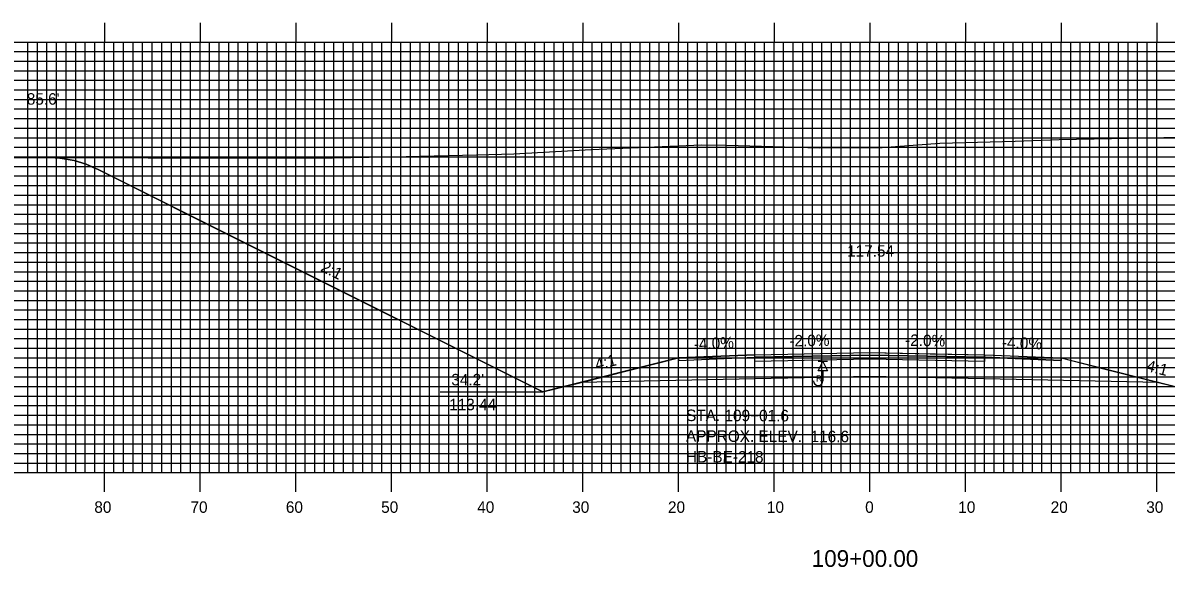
# Model space of a CAD drawing. Extents: x 1768874 to 1769217, y 442591 to 442811.
# Drawn here: x 1768951.5 to 1769071, y 442658.8 to 442715.7 of the extents above; entities that cross this region are included whole.
import ezdxf

# ---------------------------------------------------------------- set-up
doc = ezdxf.new("R2010")
doc.units = 0
for name, color, linetype in [('ANNOTATION', 7, 'Continuous'), ('BORING - REFUSAL', 7, 'Continuous'), ('D_Roadway_Centerline', 7, 'Continuous'), ('D_Roadway_Centerline_Text', 7, 'Continuous'), ('D_Roadway_Edge_Shoulder', 7, 'Continuous'), ('D_Roadway_Edge_TW', 7, 'Continuous'), ('D_Roadway_Pavement', 7, 'Continuous'), ('D_Roadway_SlopeLines', 7, 'Continuous'), ('D_Roadway_SubGrade', 7, 'Continuous'), ('D_Text_Standard', 7, 'Continuous'), ('H_V ANNOTATION', 7, 'Continuous'), ('MAJOR', 7, 'Continuous'), ('MINOR', 7, 'Continuous'), ('PDRAIN', 7, 'Continuous'), ('S_Roadway_Centerline', 7, 'Continuous')]:
    doc.layers.add(name, color=color, linetype=linetype)

msp = doc.modelspace()

# ---------------------------------------------------------------- linework, layer by layer
at = {"layer": 'BORING - REFUSAL'}
for p, q in [((1769035.57, 442680.27), (1769034.61, 442680.27)), ((1769035.09, 442679.31), (1769035.09, 442678.25))]:
    msp.add_line(p, q, dxfattribs=at)
msp.add_lwpolyline([(1769035.09, 442680.27), (1769035.57, 442679.31), (1769034.61, 442679.31)], close=True, dxfattribs=at)
msp.add_arc((1769034.6, 442678.25), 0.485, 180, 0, dxfattribs=at)
at = {"layer": 'D_Roadway_Centerline'}
msp.add_lwpolyline([(1768954.34, 442701.59), (1768955.34, 442701.52), (1768955.59, 442701.51), (1768956.84, 442701.28), (1768958.09, 442700.89), (1768958.75, 442700.6), (1768959.34, 442700.34), (1768975.05, 442692.48), (1769005.81, 442677.1), (1769009.82, 442678.1), (1769019.99, 442680.65), (1769027.99, 442680.97), (1769039.99, 442681.21), (1769046.29, 442681.08), (1769051.99, 442680.97), (1769059.99, 442680.65), (1769064.47, 442679.53), (1769070.16, 442678.1), (1769074.16, 442677.1)], dxfattribs=at)
at = {"layer": 'D_Roadway_Edge_Shoulder'}
for points in [[(1769027.99, 442680.97), (1769019.99, 442680.65), (1769019.99, 442680.4), (1769027.99, 442680.72)], [(1769051.99, 442680.97), (1769059.99, 442680.65), (1769059.99, 442680.4), (1769051.99, 442680.72)]]:
    msp.add_lwpolyline(points, close=True, dxfattribs=at)
at = {"layer": 'D_Roadway_Edge_TW'}
msp.add_lwpolyline([(1769027.99, 442680.72), (1769027.99, 442680.97), (1769039.99, 442681.21), (1769051.99, 442680.97), (1769051.99, 442680.72), (1769039.99, 442680.96)], close=True, dxfattribs=at)
at = {"layer": 'D_Roadway_Pavement'}
msp.add_lwpolyline([(1769027.99, 442680.3), (1769027.99, 442680.72), (1769039.99, 442680.96), (1769051.99, 442680.72), (1769051.99, 442680.3), (1769039.99, 442680.54)], close=True, dxfattribs=at)
at = {"layer": 'D_Roadway_SlopeLines'}
for points in [[(1769005.81, 442677.1), (1768959.34, 442700.34), (1768958.09, 442700.89), (1768956.84, 442701.28), (1768955.59, 442701.51), (1768954.34, 442701.59)], [(1769019.99, 442680.65), (1769005.81, 442677.1)], [(1769059.99, 442680.65), (1769074.16, 442677.1)]]:
    msp.add_lwpolyline(points, dxfattribs=at)
at = {"layer": 'D_Roadway_SubGrade'}
msp.add_lwpolyline([(1769027.99, 442678.47), (1769009.82, 442678.1), (1769019.99, 442680.65), (1769019.99, 442680.4), (1769027.99, 442680.72), (1769039.99, 442680.96), (1769051.99, 442680.72), (1769059.99, 442680.4), (1769059.99, 442680.65), (1769070.16, 442678.1), (1769051.99, 442678.47), (1769039.99, 442678.71)], close=True, dxfattribs=at)
at = {"layer": 'MAJOR'}
for p, q in [((1768959.99, 442715.67), (1768959.99, 442713.67)), ((1768969.99, 442715.67), (1768969.99, 442713.67)), ((1768979.99, 442715.67), (1768979.99, 442713.67)), ((1768989.99, 442715.67), (1768989.99, 442713.67)), ((1768999.99, 442715.67), (1768999.99, 442713.67)), ((1769009.99, 442715.67), (1769009.99, 442713.67)), ((1769019.99, 442715.67), (1769019.99, 442713.67)), ((1769029.99, 442715.67), (1769029.99, 442713.67)), ((1769039.99, 442715.67), (1769039.99, 442713.67)), ((1769049.99, 442715.67), (1769049.99, 442713.67)), ((1769059.99, 442715.67), (1769059.99, 442713.67)), ((1769069.99, 442715.67), (1769069.99, 442713.67)), ((1768899.99, 442713.67), (1769179.99, 442713.67)), ((1768899.99, 442713.67), (1769179.99, 442713.67)), ((1768959.99, 442668.67), (1768959.99, 442713.67)), ((1768969.99, 442668.67), (1768969.99, 442713.67)), ((1768979.99, 442668.67), (1768979.99, 442713.67)), ((1768989.99, 442668.67), (1768989.99, 442713.67)), ((1768999.99, 442668.67), (1768999.99, 442713.67)), ((1769009.99, 442668.67), (1769009.99, 442713.67)), ((1769019.99, 442668.67), (1769019.99, 442713.67)), ((1769029.99, 442668.67), (1769029.99, 442713.67)), ((1769039.99, 442668.67), (1769039.99, 442713.67)), ((1769049.99, 442668.67), (1769049.99, 442713.67)), ((1769059.99, 442668.67), (1769059.99, 442713.67)), ((1769069.99, 442668.67), (1769069.99, 442713.67)), ((1768899.99, 442708.67), (1769179.99, 442708.67)), ((1768899.99, 442703.67), (1769179.99, 442703.67)), ((1768899.99, 442698.67), (1769179.99, 442698.67)), ((1768899.99, 442693.67), (1769179.99, 442693.67)), ((1768899.99, 442688.67), (1769179.99, 442688.67)), ((1768899.99, 442683.67), (1769179.99, 442683.67)), ((1768899.99, 442678.67), (1769179.99, 442678.67)), ((1768899.99, 442673.67), (1769179.99, 442673.67)), ((1768899.99, 442668.67), (1769179.99, 442668.67)), ((1768899.99, 442668.67), (1769179.99, 442668.67)), ((1768959.99, 442666.66), (1768959.99, 442668.67)), ((1768969.99, 442666.66), (1768969.99, 442668.67)), ((1768979.99, 442666.66), (1768979.99, 442668.67)), ((1768989.99, 442666.66), (1768989.99, 442668.67)), ((1768999.99, 442666.66), (1768999.99, 442668.67)), ((1769009.99, 442666.66), (1769009.99, 442668.67)), ((1769019.99, 442666.66), (1769019.99, 442668.67)), ((1769029.99, 442666.66), (1769029.99, 442668.67)), ((1769039.99, 442666.66), (1769039.99, 442668.67)), ((1769049.99, 442666.66), (1769049.99, 442668.67)), ((1769059.99, 442666.66), (1769059.99, 442668.67)), ((1769069.99, 442666.66), (1769069.99, 442668.67))]:
    msp.add_line(p, q, dxfattribs=at)
at = {"layer": 'MINOR'}
for p, q in [((1768951.99, 442668.67), (1768951.99, 442713.67)), ((1768952.99, 442668.67), (1768952.99, 442713.67)), ((1768953.99, 442668.67), (1768953.99, 442713.67)), ((1768954.99, 442668.67), (1768954.99, 442713.67)), ((1768955.99, 442668.67), (1768955.99, 442713.67)), ((1768956.99, 442668.67), (1768956.99, 442713.67)), ((1768957.99, 442668.67), (1768957.99, 442713.67)), ((1768958.99, 442668.67), (1768958.99, 442713.67)), ((1768960.99, 442668.67), (1768960.99, 442713.67)), ((1768961.99, 442668.67), (1768961.99, 442713.67)), ((1768962.99, 442668.67), (1768962.99, 442713.67)), ((1768963.99, 442668.67), (1768963.99, 442713.67)), ((1768964.99, 442668.67), (1768964.99, 442713.67)), ((1768965.99, 442668.67), (1768965.99, 442713.67)), ((1768966.99, 442668.67), (1768966.99, 442713.67)), ((1768967.99, 442668.67), (1768967.99, 442713.67)), ((1768968.99, 442668.67), (1768968.99, 442713.67)), ((1768970.99, 442668.67), (1768970.99, 442713.67)), ((1768971.99, 442668.67), (1768971.99, 442713.67)), ((1768972.99, 442668.67), (1768972.99, 442713.67)), ((1768973.99, 442668.67), (1768973.99, 442713.67)), ((1768974.99, 442668.67), (1768974.99, 442713.67)), ((1768975.99, 442668.67), (1768975.99, 442713.67)), ((1768976.99, 442668.67), (1768976.99, 442713.67)), ((1768977.99, 442668.67), (1768977.99, 442713.67)), ((1768978.99, 442668.67), (1768978.99, 442713.67)), ((1768980.99, 442668.67), (1768980.99, 442713.67)), ((1768981.99, 442668.67), (1768981.99, 442713.67)), ((1768982.99, 442668.67), (1768982.99, 442713.67)), ((1768983.99, 442668.67), (1768983.99, 442713.67)), ((1768984.99, 442668.67), (1768984.99, 442713.67)), ((1768985.99, 442668.67), (1768985.99, 442713.67)), ((1768986.99, 442668.67), (1768986.99, 442713.67)), ((1768987.99, 442668.67), (1768987.99, 442713.67)), ((1768988.99, 442668.67), (1768988.99, 442713.67)), ((1768990.99, 442668.67), (1768990.99, 442713.67)), ((1768991.99, 442668.67), (1768991.99, 442713.67)), ((1768992.99, 442668.67), (1768992.99, 442713.67)), ((1768993.99, 442668.67), (1768993.99, 442713.67)), ((1768994.99, 442668.67), (1768994.99, 442713.67)), ((1768995.99, 442668.67), (1768995.99, 442713.67)), ((1768996.99, 442668.67), (1768996.99, 442713.67)), ((1768997.99, 442668.67), (1768997.99, 442713.67)), ((1768998.99, 442668.67), (1768998.99, 442713.67)), ((1769000.99, 442668.67), (1769000.99, 442713.67)), ((1769001.99, 442668.67), (1769001.99, 442713.67)), ((1769002.99, 442668.67), (1769002.99, 442713.67)), ((1769003.99, 442668.67), (1769003.99, 442713.67)), ((1769004.99, 442668.67), (1769004.99, 442713.67)), ((1769005.99, 442668.67), (1769005.99, 442713.67)), ((1769006.99, 442668.67), (1769006.99, 442713.67)), ((1769007.99, 442668.67), (1769007.99, 442713.67)), ((1769008.99, 442668.67), (1769008.99, 442713.67)), ((1769010.99, 442668.67), (1769010.99, 442713.67)), ((1769011.99, 442668.67), (1769011.99, 442713.67)), ((1769012.99, 442668.67), (1769012.99, 442713.67)), ((1769013.99, 442668.67), (1769013.99, 442713.67)), ((1769014.99, 442668.67), (1769014.99, 442713.67)), ((1769015.99, 442668.67), (1769015.99, 442713.67)), ((1769016.99, 442668.67), (1769016.99, 442713.67)), ((1769017.99, 442668.67), (1769017.99, 442713.67)), ((1769018.99, 442668.67), (1769018.99, 442713.67)), ((1769020.99, 442668.67), (1769020.99, 442713.67)), ((1769021.99, 442668.67), (1769021.99, 442713.67)), ((1769022.99, 442668.67), (1769022.99, 442713.67)), ((1769023.99, 442668.67), (1769023.99, 442713.67)), ((1769024.99, 442668.67), (1769024.99, 442713.67)), ((1769025.99, 442668.67), (1769025.99, 442713.67)), ((1769026.99, 442668.67), (1769026.99, 442713.67)), ((1769027.99, 442668.67), (1769027.99, 442713.67)), ((1769028.99, 442668.67), (1769028.99, 442713.67)), ((1769030.99, 442668.67), (1769030.99, 442713.67)), ((1769031.99, 442668.67), (1769031.99, 442713.67)), ((1769032.99, 442668.67), (1769032.99, 442713.67)), ((1769033.99, 442668.67), (1769033.99, 442713.67)), ((1769034.99, 442668.67), (1769034.99, 442713.67)), ((1769035.99, 442668.67), (1769035.99, 442713.67)), ((1769036.99, 442668.67), (1769036.99, 442713.67)), ((1769037.99, 442668.67), (1769037.99, 442713.67)), ((1769038.99, 442668.67), (1769038.99, 442713.67)), ((1769040.99, 442668.67), (1769040.99, 442713.67)), ((1769041.99, 442668.67), (1769041.99, 442713.67)), ((1769042.99, 442668.67), (1769042.99, 442713.67)), ((1769043.99, 442668.67), (1769043.99, 442713.67)), ((1769044.99, 442668.67), (1769044.99, 442713.67)), ((1769045.99, 442668.67), (1769045.99, 442713.67)), ((1769046.99, 442668.67), (1769046.99, 442713.67)), ((1769047.99, 442668.67), (1769047.99, 442713.67)), ((1769048.99, 442668.67), (1769048.99, 442713.67)), ((1769050.99, 442668.67), (1769050.99, 442713.67)), ((1769051.99, 442668.67), (1769051.99, 442713.67)), ((1769052.99, 442668.67), (1769052.99, 442713.67)), ((1769053.99, 442668.67), (1769053.99, 442713.67)), ((1769054.99, 442668.67), (1769054.99, 442713.67)), ((1769055.99, 442668.67), (1769055.99, 442713.67)), ((1769056.99, 442668.67), (1769056.99, 442713.67)), ((1769057.99, 442668.67), (1769057.99, 442713.67)), ((1769058.99, 442668.67), (1769058.99, 442713.67)), ((1769060.99, 442668.67), (1769060.99, 442713.67)), ((1769061.99, 442668.67), (1769061.99, 442713.67)), ((1769062.99, 442668.67), (1769062.99, 442713.67)), ((1769063.99, 442668.67), (1769063.99, 442713.67)), ((1769064.99, 442668.67), (1769064.99, 442713.67)), ((1769065.99, 442668.67), (1769065.99, 442713.67)), ((1769066.99, 442668.67), (1769066.99, 442713.67)), ((1769067.99, 442668.67), (1769067.99, 442713.67)), ((1769068.99, 442668.67), (1769068.99, 442713.67)), ((1768899.99, 442712.67), (1769179.99, 442712.67)), ((1768899.99, 442711.67), (1769179.99, 442711.67)), ((1768899.99, 442710.67), (1769179.99, 442710.67)), ((1768899.99, 442709.67), (1769179.99, 442709.67)), ((1768899.99, 442707.67), (1769179.99, 442707.67)), ((1768899.99, 442706.67), (1769179.99, 442706.67)), ((1768899.99, 442705.67), (1769179.99, 442705.67)), ((1768899.99, 442704.67), (1769179.99, 442704.67)), ((1768899.99, 442702.67), (1769179.99, 442702.67)), ((1768899.99, 442701.67), (1769179.99, 442701.67)), ((1768899.99, 442700.67), (1769179.99, 442700.67)), ((1768899.99, 442699.67), (1769179.99, 442699.67)), ((1768899.99, 442697.67), (1769179.99, 442697.67)), ((1768899.99, 442696.67), (1769179.99, 442696.67)), ((1768899.99, 442695.67), (1769179.99, 442695.67)), ((1768899.99, 442694.67), (1769179.99, 442694.67)), ((1768899.99, 442692.67), (1769179.99, 442692.67)), ((1768899.99, 442691.67), (1769179.99, 442691.67)), ((1768899.99, 442690.67), (1769179.99, 442690.67)), ((1768899.99, 442689.67), (1769179.99, 442689.67)), ((1768899.99, 442687.67), (1769179.99, 442687.67)), ((1768899.99, 442686.67), (1769179.99, 442686.67)), ((1768899.99, 442685.67), (1769179.99, 442685.67)), ((1768899.99, 442684.67), (1769179.99, 442684.67)), ((1768899.99, 442682.67), (1769179.99, 442682.67)), ((1768899.99, 442681.67), (1769179.99, 442681.67)), ((1768899.99, 442680.67), (1769179.99, 442680.67)), ((1768899.99, 442679.67), (1769179.99, 442679.67)), ((1768899.99, 442677.67), (1769179.99, 442677.67)), ((1768899.99, 442676.67), (1769179.99, 442676.67)), ((1768899.99, 442675.67), (1769179.99, 442675.67)), ((1768899.99, 442674.67), (1769179.99, 442674.67)), ((1768899.99, 442672.67), (1769179.99, 442672.67)), ((1768899.99, 442671.67), (1769179.99, 442671.67)), ((1768899.99, 442670.67), (1769179.99, 442670.67)), ((1768899.99, 442669.67), (1769179.99, 442669.67))]:
    msp.add_line(p, q, dxfattribs=at)
at = {"layer": 'PDRAIN'}
msp.add_line((1768995.09, 442677.1), (1769005.81, 442677.1), dxfattribs=at)
at = {"layer": 'S_Roadway_Centerline'}
msp.add_lwpolyline([(1768945.8, 442701.58), (1768962.04, 442701.59), (1768964.58, 442701.57), (1768969.93, 442701.58), (1768983.85, 442701.58), (1768991.54, 442701.69), (1768998.89, 442701.88), (1769002.77, 442701.97), (1769010.86, 442702.42), (1769022.45, 442702.93), (1769025, 442702.88), (1769034.72, 442702.6), (1769041.28, 442702.64), (1769047.32, 442703.09), (1769055.18, 442703.31), (1769059.78, 442703.48), (1769070.74, 442703.68), (1769079.89, 442703.75)], dxfattribs=at)

# ---------------------------------------------------------------- texts
at = {"layer": 'ANNOTATION'}
for s, rotation, p in [('2:1', 333.4353, (1768982.51, 442689.79)), ('-4.0%', 2.2905, (1769021.62, 442681.51)), ('-2.0%', 1.1458, (1769031.6, 442681.84)), ('-2.0%', 358.8542, (1769043.67, 442681.93)), ('-4.0%', 357.7095, (1769053.78, 442681.7)), ('4:1', 14.0381, (1769011.44, 442679.37)), ('4:1', 345.963, (1769068.82, 442679.3))]:
    msp.add_text(s, height=1.2, rotation=rotation, dxfattribs=at).set_placement(p)
for s, p in [("34.2'", (1768996.25, 442677.79)), ('113.44', (1768996.03, 442675.19))]:
    msp.add_text(s, height=1.2, dxfattribs=at).set_placement(p)
at = {"layer": 'BORING - REFUSAL'}
msp.add_text('R', height=0.64, dxfattribs=at).set_placement((1769034.38, 442678.19))
for s, p in [('STA. 109+01.6', (1769020.79, 442674.06)), ('APPROX. ELEV.  116.6', (1769020.78, 442671.9)), ('HB-BE-218', (1769020.77, 442669.74))]:
    msp.add_text(s, height=1.2, rotation=359.8142, dxfattribs=at).set_placement(p)
at = {"layer": 'D_Roadway_Centerline'}
for s, p in [('C', (1769039.98, 442681.21)), ('L', (1769039.99, 442681.2))]:
    msp.add_text(s, height=0.0146, dxfattribs=at).set_placement(p)
at = {"layer": 'D_Roadway_Centerline_Text'}
msp.add_text('117.54', height=1.2, dxfattribs=at).set_placement((1769037.62, 442691.24))
at = {"layer": 'D_Text_Standard'}
msp.add_text("85.6'", height=1.2, dxfattribs=at).set_placement((1768951.88, 442707.12))
at = {"layer": 'H_V ANNOTATION'}
for s, height, p in [('80', 1.2, (1768958.94, 442664.47)), ('70', 1.2, (1768968.99, 442664.47)), ('60', 1.2, (1768978.96, 442664.47)), ('50', 1.2, (1768988.92, 442664.47)), ('40', 1.2, (1768998.96, 442664.47)), ('30', 1.2, (1769008.89, 442664.47)), ('20', 1.2, (1769018.9, 442664.47)), ('10', 1.2, (1769029.24, 442664.47)), ('0', 1.2, (1769039.51, 442664.47)), ('10', 1.2, (1769049.24, 442664.47)), ('20', 1.2, (1769058.9, 442664.47)), ('30', 1.2, (1769068.89, 442664.47)), ('109+00.00', 1.75, (1769033.93, 442658.82))]:
    msp.add_text(s, height=height, dxfattribs=at).set_placement(p)

doc.saveas('drawing.dxf')
